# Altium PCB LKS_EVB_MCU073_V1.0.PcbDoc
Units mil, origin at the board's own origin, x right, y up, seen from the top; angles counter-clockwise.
Board outline 2625 x 1560 mil, 2 copper layers (Top Layer, Bottom Layer); 24 components, 50 nets, 124 pads, 29 vias.
Unrouted connection lines stored in the file: 4.
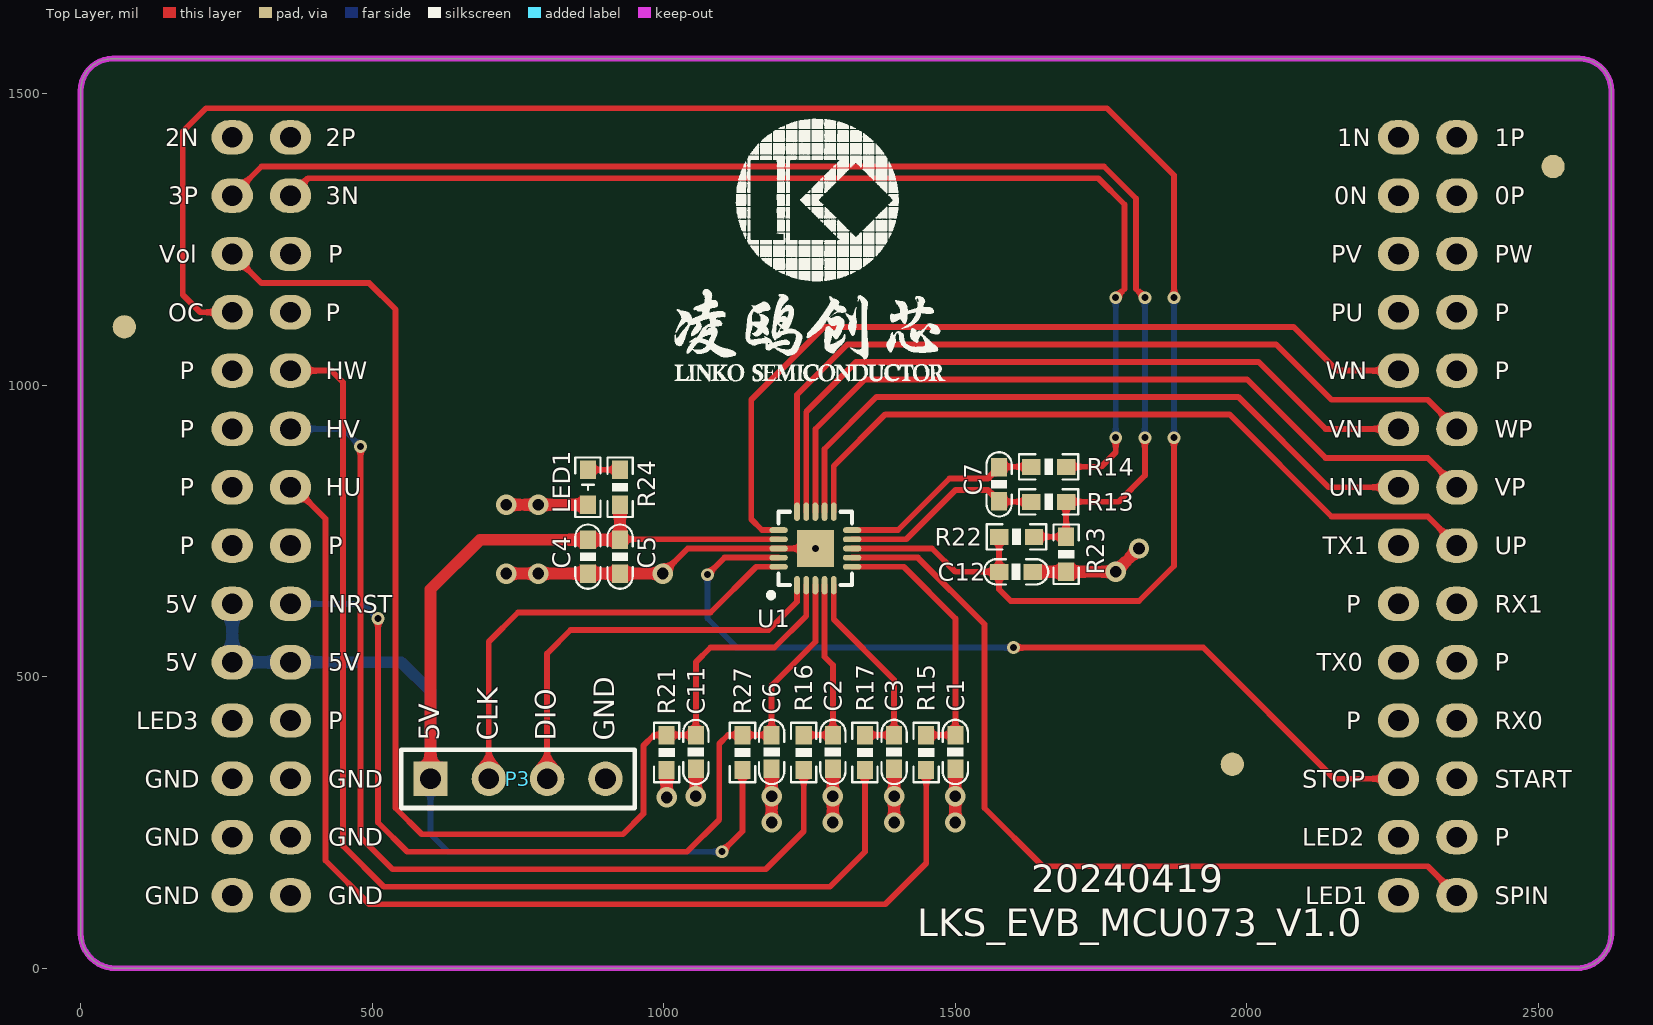
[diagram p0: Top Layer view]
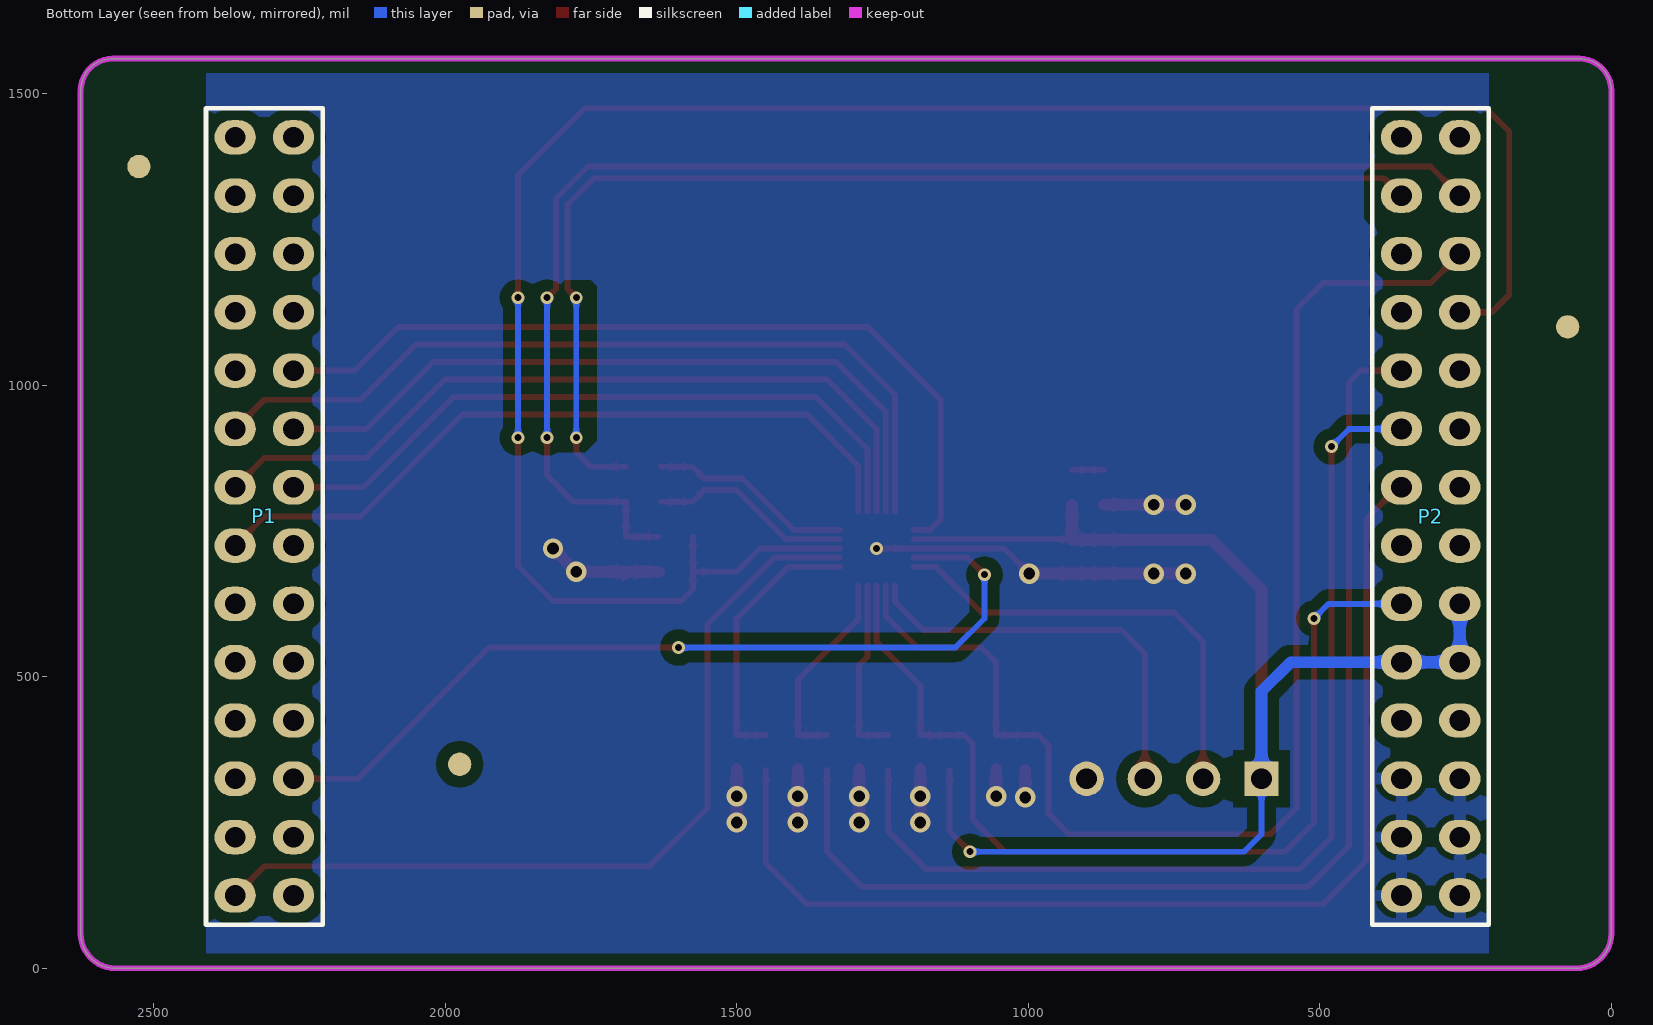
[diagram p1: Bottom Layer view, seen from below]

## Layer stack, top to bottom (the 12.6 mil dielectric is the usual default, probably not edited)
Top Solder: solder mask 0.4, Solder Resist, Dk 3.5
Top Layer: signal copper 1.4
Dielectric1: dielectric 12.6, FR-4, Dk 4.8
Bottom Layer: signal copper 1.4
Bottom Solder: solder mask 0.4, Solder Resist, Dk 3.5

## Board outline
0,60 0,1505 cw(c55,1505) 55,1560 2570,1560 cw(c2570,1505) 2625,1505 2625,60 cw(c2565,60) 2565,0 60,0 cw(c60,60)

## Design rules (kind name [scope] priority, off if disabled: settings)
Clearance Clearance_2 [InPolygon] p1: gap=20 ignorepadtopadclearanceinfootprint=FALSE except(0: Arc-Hole Track-Hole SMDPad-Hole THPad-Hole Via-Hole Fill-Hole Poly-Hole Region-Hole Text-Hole)
Clearance Clearance_1 [All] p2: gap=0 ignorepadtopadclearanceinfootprint=FALSE
ComponentClearance [All] p1: gap=0 collisioncheckmode=3 verticalgap=0 showdistances=FALSE
FabricationTestpoint [(IsPad And (OnTopLayer Or OnBottomLayer))] p1: side=3 testpointundercomponent=TRUE minsize=40 maxsize=100 preferedsize=60 minholesize=0 maxholesize=40 preferedholesize=32 testpointgrid=1 allowsidetop=TRUE allowsidebottom=TRUE usegrid=TRUE gridtolerance=0.01
HoleSize [All] p1: absolutevalues=TRUE maxlimit=100 minlimit=0 maxpercent=80.000 minpercent=20.000
PolygonConnect PolygonConnect_1 [HasFootprint('HDR 2X14 底层') vs InNet('GND')] p1: connectstyle=Relief reliefconductorwidth=20 reliefentries=4 polygonreliefangle="90 Angle" airgapwidth=10
PolygonConnect [All] p2: connectstyle=Direct reliefconductorwidth=10 reliefentries=4 polygonreliefangle="90 Angle" airgapwidth=10
RoutingVias [All] p1: holewidth=28 width=50 viastyle="Through Hole" minholewidth=0 minwidth=10 maxholewidth=28 maxwidth=50
SilkToSolderMaskClearance SilkscreenOverComponentPads [IsPad] p1: minsilkscreentomaskgap=10 clearancetoexposedcopper=TRUE
SolderMaskExpansion [All] p1: expansion=4 istentingtop=FALSE
Width [All] p1: maxlimit=100 minlimit=1 preferedwidth=10
26 further rules are at their usual default settings.

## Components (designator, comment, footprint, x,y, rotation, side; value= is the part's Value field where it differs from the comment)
C1 "10nF/16V" 0603C 1500,371 r270 top
C2 "10nF/16V" 0603C 1290,371 r270 top
C3 "10nF/16V" 0603C 1395,371 r270 top
C4 "10uF/25V" 0603C 870,705.95 r90 top
C5 "100nF/50V" 0603C 925,705.95 r90 top
C6 "100nF/50V" 0603C 1185,371 r270 top
C7 "1nF/50V" 0603C 1575,830 r90 top
C11 "100nF/50V" 0603C 1055,370.95 r90 top
C12 "1nF/50V" 0603C 1604.05,680 r180 top
LED1 "LED" "LED 0603R" 870,825 r270 top
P1 "Header 14X2A" "HDR 2X14 底层" 2260,1425 r180 bottom locked
P2 "Header 14X2A" "HDR 2X14 底层" 260,1425 r180 bottom locked
P3 "Header 4" HDR1X4 600,325 r0 top
R13 "1K1%" 0603R 1660,800 r180 top value=K
R14 "1K1%" 0603R 1660,860 r180 top value=K
R15 "2K" 0603R 1450,370 r90 top value=K
R16 "2K" 0603R 1240,370 r90 top value=K
R17 "2K" 0603R 1345,370 r90 top value=K
R21 "1K1%" 0603R 1005,370 r90 top value=K
R22 "1K1%" 0603R 1605,740 r0 top value=K
R23 "10R" 0603R 1690,710 r270 top value=K
R24 "330R" 0603R 925,825 r90 top value=K
R27 "20K1%" 0603R 1135,370 r270 top value=K
U1 "LKS32MC073HBQ8" QFN20_3X3 1260,720 r0 top locked

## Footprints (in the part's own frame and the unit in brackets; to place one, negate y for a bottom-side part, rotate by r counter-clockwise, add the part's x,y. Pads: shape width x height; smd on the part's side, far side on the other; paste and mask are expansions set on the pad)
0603C [mm] "电容"
  rect 0.8x0.7 smd: 1(-0.737,0) 2(0.738,0)
  silkscreen extent -1.4,-0.55 1.4,0.55, body extent -0.8,-0.41 0.8,0.41, height 0.81
0603R [mm] "电阻"
  rect 0.8x0.7 smd: 1(-0.762,0) 2(0.762,0)
  silkscreen extent -1.3,-0.55 1.3,0.55, body extent -0.8,-0.4 0.8,0.4, height 0.45
HDR1X4 [mm] "Connector; Header; 4 Position"
  rect 1.5x1.5 hole 0.9: 1(0,0)
  round 1.5 hole 0.9: 2(2.54,0) 3(5.08,0) 4(7.62,0)
  silkscreen extent -1.27,-1.27 8.89,1.27
"HDR 2X14 底层" [mm] "双排针 2.54mm 底层"
  oval 1.8x1.5 hole 0.9: 1(0,0) 2(0,-2.54) 3(0,-5.08) 4(0,-7.62) 5(0,-10.16) 6(0,-12.7) 7(0,-15.24) 8(0,-17.78) 9(0,-20.32) 10(0,-22.86) 11(0,-25.4) 12(0,-27.94) 13(0,-30.48) 14(0,-33.02) 15(-2.54,0) 16(-2.54,-2.54) 17(-2.54,-5.08) 18(-2.54,-7.62) 19(-2.54,-10.16) 20(-2.54,-12.7) 21(-2.54,-15.24) 22(-2.54,-17.78) 23(-2.54,-20.32) 24(-2.54,-22.86) 25(-2.54,-25.4) 26(-2.54,-27.94) 27(-2.54,-30.48) 28(-2.54,-33.02)
  silkscreen extent -3.81,-34.29 1.27,1.27, body extent -3.81,-34.29 1.27,1.27, height 8.5
"LED 0603R" [mm] "LED"
  rect 0.8x0.7 smd: 1(-0.762,0) 2(0.762,0)
  silkscreen extent -1.3,-0.55 1.3,0.55, body extent -0.8,-0.4 0.8,0.4, height 0.47
QFN20_3X3 [mm] "芯片"
  oval 0.25x0.8 smd: 1(-0.8,-1.6) 2(-0.4,-1.6) 3(0,-1.6) 4(0.4,-1.6) 5(0.8,-1.6) 11(0.8,1.6) 12(0.4,1.6) 13(0,1.6) 14(-0.4,1.6) 15(-0.8,1.6)
  oval 0.8x0.25 smd: 6(1.6,-0.8) 7(1.6,-0.4) 8(1.6,0) 9(1.6,0.4) 10(1.6,0.8) 16(-1.6,0.8) 17(-1.6,0.4) 18(-1.6,0) 19(-1.6,-0.4) 20(-1.6,-0.8)
  rect 1.6x1.6 smd: 21(0,0)
  silkscreen extent -2.03,-2.13 1.6,1.6, body extent -1.47,-1.5 1.53,1.5, height 0.63

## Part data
C1 C2 C3: library part CAP, "Capacitor"
C4 C5 C6 C7 C11 C12: library part C, "Capacitor"
LED1: "LED_Light"
P1 P2: "Header, 14-Pin, Dual row"
P3: "Header, 4-Pin"
R13 R14 R15 R16 R17 R21 R22 R23 R24 R27: library part Res, "Resistor"
U1: "芯片"

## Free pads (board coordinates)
  round 40 all layers, no hole: 0(2525,1375) 1(75,1100) 2(1975,350)

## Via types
v1: diameter 35, hole 20, Top Layer to Bottom Layer, 17 vias
v2: diameter 22, hole 12, Top Layer to Bottom Layer, 12 vias

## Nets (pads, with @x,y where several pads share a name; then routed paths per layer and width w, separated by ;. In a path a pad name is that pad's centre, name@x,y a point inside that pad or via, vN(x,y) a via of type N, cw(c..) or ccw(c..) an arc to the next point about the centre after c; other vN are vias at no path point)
+5V: C4.2 C5.2 P2.9 P2.10 P2.24 P3.1 R24.1 R27.2 U1.17 | length 2390.2
  Top Layer w10: C5.2 925.75,735.75 U1.17 ; v2(1100,200) 1135,235 R27.2
  Top Layer w20: P3.1 600,650 685,735 C4.2 C5.2 R24.1
  Bottom Layer w10: P3.1 600,230 630,200 v2(1100,200)
  Bottom Layer w20: P2.9 P2.10 P2.24 550,525 600,475 P3.1
GND: C1.2 C2.2 C3.2 C4.1 C5.1 C6.2 C11.1 C12.1 LED1.2 P2.12 P2.13 P2.14 P2.16 P2.26 P2.27 P2.28 P3.4 R14.1 R21.1 R23.2 U1.18 U1.21 | length 3343.4
  Top Layer w10: P2.16 390,1355 1745,1355 1790,1310 1790,1165 v2(1775,1150) ; v1(998.05,676.95) 1041.11,720 U1.18 v2(1260,720) ; R14.1 1750,860 1775,885 v2(1775,910)
  Top Layer w20: v1(730,676.95) v1(785,676.95) C4.1 C5.1 v1(998.05,676.95) ; v1(730,795) v1(785,795) LED1.2 ; v1(1005,293.06) R21.1 ; v1(1055,295) C11.1 ; v1(1185,250) v1(1185,295) C6.2 ; v1(1290,250) v1(1290,295) C2.2 ; v1(1395,250) v1(1395,295) C3.2 ; v1(1500,250) v1(1500,295) C1.2 ; C12.1 R23.2 1690,678.78 1693.78,675 1693.78,680 v1(1775,680) v1(1815,720)
  Bottom Layer w10: v2(1775,910) v2(1775,1150)
HALL_U: C1.1 R15.2 U1.6 | length 463.7
  Top Layer w10: U1.6 1411.5,688.5 1500,600 C1.1 R15.2
HALL_V: C2.1 R16.2 U1.4 | length 312.9
  Top Layer w10: R16.2 C2.1 1290,520 1275.75,534.25 U1.4
HALL_W: C3.1 R17.2 U1.5 | length 349.9
  Top Layer w10: U1.5 1291.5,598.5 1395,495 C3.1 R17.2
HU: P2.21 R15.1 | length 1918.4
  Top Layer w10: P2.21 365.91,825 420,770.91 420,185 495,110 1380,110 1450,180 R15.1
HV: P2.20 R16.1 | length 1717.1
  Top Layer w10: v2(480,895) 480,225 535,170 1175,170 1240,235 R16.1
  Bottom Layer w10: P2.20 450,925 v2(480,895)
HW: P2.19 R17.1 | length 1982.1
  Top Layer w10: P2.19 430,1025 450,1005 450,210 520,140 1285,140 1345,200 R17.1
LED1: P1.14
LED2: P1.13
LED3: P2.11
NetLED1_1: LED1.1 R24.2 | length 55
  Top Layer w10: LED1.1 R24.2
NRST: C6.1 P2.23 R27.1 U1.3 | length 1653.1
  Top Layer w10: v2(510,600) 510,250 560,200 1040,200 1095,255 1095,385 1110,400 R27.1 C6.1 1185,485 1260,560 U1.3
  Bottom Layer w10: P2.23 485,625 v2(510,600)
OC: C12.2 P2.4 R22.1 U1.8 | length 3503.3
  Top Layer w10: P2.4 205,1125 175,1155 175,1435 215,1475 1760,1475 1875,1360 v2(1875,1150) ; U1.8 1460,720 1500,680 C12.2 ; R22.1 C12.2 ; v2(1875,910) 1875,690 1815,630 1595,630 1575,650 C12.2
  Bottom Layer w10: v2(1875,910) v2(1875,1150)
OPA1_IN: C7.2 R14.2 U1.10 | length 352
  Top Layer w10: U1.10 1401.5,751.5 1490,840 1555.94,840 C7.2 1575.94,860 R14.2
OPA1_IP: C7.1 R13.2 U1.9 | length 350.2
  Top Layer w10: U1.9 1415.75,735.75 1500,820 1556,820 C7.1 1576,800 R13.2
P0.0: P2.22
P0.4: P1.27
P0.14: P1.11
P1.3: P1.24
P1.10: P1.19
P1.11: P1.18
P2.2: P2.18
P2.3: P2.5
P2.7: P1.9
P2.10: P2.17
P3.2: P2.25
PGND: P1.1 P1.2 P2.1 P2.2 R13.1 R22.2 R23.1 | length 2343.3
  Top Layer w10: P2.2 310,1375 1755,1375 1810,1320 1810,1165 v2(1825,1150) ; R22.2 R23.1 R13.1 1780,800 1825,845 v2(1825,910)
  Bottom Layer w10: v2(1825,910) v2(1825,1150)
PU: P1.4
PV: P1.3
PW: P1.17
RXD0: P1.25
RXD1: P1.23
SPIN: P1.28 U1.7 | length 1461.5
  Top Layer w10: U1.7 1435.75,704.25 1550,590 1550,275 1650,175 2310,175 P1.28
START1: P1.26
STOP1: P1.12 U1.19 | length 1508
  Top Layer w10: v2(1075,675) 1104.25,704.25 U1.19 ; v2(1600,550) 1925,550 2150,325 P1.12
  Bottom Layer w10: v2(1075,675) 1075,600 1125,550 v2(1600,550)
SWCLK: P3.2 U1.20 | length 785.2
  Top Layer w10: P3.2 700,560 750,610 1080,610 1158.5,688.5 U1.20
SWDIO: P3.3 U1.1 | length 708.7
  Top Layer w10: P3.3 800,540 840,580 1180,580 1228.5,628.5 U1.1
TXD0: P1.10
TXD1: P1.8
UN: P1.7 U1.12 | length 1193.2
  Top Layer w10: U1.12 1275.75,890.75 1365,980 1985,980 2140,825 P1.7
UP: P1.22 U1.11 | length 1276.9
  Top Layer w10: U1.11 1291.5,861.5 1380,950 1970,950 2145,775 2309.99,775 P1.22
UP-: P2.15
VN: P1.6 U1.14 | length 1270.2
  Top Layer w10: U1.14 1244.25,954.25 1330,1040 2020,1040 2135,925 P1.6
VOL_ADC: C11.2 P2.3 R21.2 U1.2 | length 2246.6
  Top Layer w10: P2.3 310,1175 495,1175 540,1130 540,275 585,230 930,230 965,265 965,381.65 983.35,400 R21.2 C11.2 1055,525 1080,550 1190,550 1244.25,604.25 U1.2
VP: P1.21 U1.13 | length 1353.8
  Top Layer w10: U1.13 1260,925 1345,1010 2000,1010 2135,875 2310,875 P1.21
VP-: P1.15
WN: P1.5 U1.16 | length 1452.5
  Top Layer w10: U1.16 1168.5,751.5 1150,770 1150,975 1275,1100 2080,1100 2155,1025 P1.5
WP: P1.20 U1.15 | length 1427.9
  Top Layer w10: U1.15 1228.5,983.5 1315,1070 2050,1070 2145,975 2309.99,975 P1.20
WP-: P1.16
pads on no net: P2.6 P2.7 P2.8

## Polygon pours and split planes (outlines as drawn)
GND on Bottom Layer "Bottom Layer-No Net 1" (solid, remove dead copper, pour order 12): 210,1560 210,0 2410,0 2410,1560

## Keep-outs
Keep-Out Layer:
  the board outline again, w10

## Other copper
Bottom Layer:
  pour cut-out: 1825,1150 1795,1180 1750,1180 1740,1170 1740,905 1760,885 1815,885 1825,895
  pour cut-out: 210,1380.02 409.98,1380.02 425,1365 425,1285 415,1275 210,1275

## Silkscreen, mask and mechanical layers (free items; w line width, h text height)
Top Overlay:
  drawing of 144 lines, arcs and shapes, not listed
  text "2N" at 145,1410 h30
  text "2P" at 420,1410 h30
  text "1N" at 2155,1410 h30
  text "1P" at 2425,1410 h30
  text "3P" at 150,1310 h30
  text "3N" at 420,1310 h30
  text "0N" at 2150,1310 h30
  text "0P" at 2425,1310 h30
  text "Vol" at 135,1210 h30
  text "P" at 425,1210 h30
  text "PV" at 2145,1210 h30
  text "PW" at 2425,1210 h30
  text "OC" at 150,1110 h30
  text "P" at 420,1110 h30
  text "PU" at 2145,1110 h30
  text "P" at 2425,1110 h30
  text "P" at 170,1010 h30
  text "HW" at 420,1010 h30
  text "WN" at 2135,1010 h30
  text "P" at 2425,1010 h30
  text "P" at 170,910 h30
  text "HV" at 420,910 h30
  text "VN" at 2140,910 h30
  text "WP" at 2425,910 h30
  text "P" at 170,810 h30
  text "HU" at 420,810 h30
  text "UN" at 2140,810 h30
  text "VP" at 2425,810 h30
  text "P" at 170,710 h30
  text "P" at 425,710 h30
  text "TX1" at 2130,710 h30
  text "UP" at 2425,710 h30
  text "5V" at 145,610 h30
  text "NRST" at 425,610 h30
  text "P" at 2170,610 h30
  text "RX1" at 2425,610 h30
  text "5V" at 145,510 h30
  text "5V" at 425,510 h30
  text "TX0" at 2120,510 h30
  text "P" at 2425,510 h30
  text "LED3" at 95,410 h30
  text "P" at 425,410 h30
  text "P" at 2170,410 h30
  text "RX0" at 2425,410 h30
  text "5V" at 615,390 h35 r90
  text "CLK" at 715,390 h35 r90
  text "DIO" at 815,390 h35 r90
  text "GND" at 915,390 h35 r90
  text "GND" at 110,310 h30
  text "GND" at 425,310 h30
  text "STOP" at 2095,310 h30
  text "START" at 2425,310 h30
  text "GND" at 110,210 h30
  text "GND" at 425,210 h30
  text "LED2" at 2095,210 h30
  text "P" at 2425,210 h30
  text "20240419" at 1630,115 h80
  text "GND" at 110,110 h30
  text "GND" at 425,110 h30
  text "LED1" at 2100,110 h30
  text "SPIN" at 2425,110 h30
  text "LKS_EVB_MCU073_V1.0" at 1435,40 h80
Top Solder:
  circle w78: c2525,1375 r17
  circle w78: c75,1100 r17
  circle w78: c1975,350 r17
Mechanical 1:
  the board outline again, w10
